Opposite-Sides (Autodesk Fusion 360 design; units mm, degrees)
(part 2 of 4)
sketch "Roller compensated wide travel cam" plane through (7, 0, 0) normal (1, 0, 0) x axis (0, 0, -1)
  line L1 (-46.7858, 45.5639) -> (-46.9806, 45.5802)
  line L2 (-46.6024, 45.5464) -> (-46.7858, 45.5639)
  line L3 (-46.4304, 45.5278) -> (-46.6024, 45.5464)
  line L4 (-46.2696, 45.5078) -> (-46.4304, 45.5278)
  line L5 (-46.1199, 45.4865) -> (-46.2696, 45.5078)
  line L6 (-45.9808, 45.464) -> (-46.1199, 45.4865)
  line L7 (-45.8519, 45.4403) -> (-45.9808, 45.464)
  line L8 (-45.7328, 45.4155) -> (-45.8519, 45.4403)
  line L9 (-45.6227, 45.3897) -> (-45.7328, 45.4155)
  line L10 (-45.5208, 45.363) -> (-45.6227, 45.3897)
  line L11 (-45.4263, 45.3354) -> (-45.5208, 45.363)
  line L12 (-45.3379, 45.3069) -> (-45.4263, 45.3354)
  line L13 (-45.2547, 45.2772) -> (-45.3379, 45.3069)
  line L14 (-45.1753, 45.2462) -> (-45.2547, 45.2772)
  line L15 (-45.0985, 45.2134) -> (-45.1753, 45.2462)
  line L16 (-45.023, 45.1784) -> (-45.0985, 45.2134)
  line L17 (-44.9476, 45.1406) -> (-45.023, 45.1784)
  line L18 (-44.8711, 45.0992) -> (-44.9476, 45.1406)
  line L19 (-44.7923, 45.0536) -> (-44.8711, 45.0992)
  line L20 (-44.7102, 45.0028) -> (-44.7923, 45.0536)
  line L21 (-44.6241, 44.9462) -> (-44.7102, 45.0028)
  line L22 (-44.5331, 44.8829) -> (-44.6241, 44.9462)
  line L23 (-44.4367, 44.8122) -> (-44.5331, 44.8829)
  line L24 (-44.3343, 44.7335) -> (-44.4367, 44.8122)
  line L25 (-44.2256, 44.6462) -> (-44.3343, 44.7335)
  line L26 (-44.1102, 44.5498) -> (-44.2256, 44.6462)
  line L27 (-43.988, 44.4442) -> (-44.1102, 44.5498)
  line L28 (-43.8587, 44.329) -> (-43.988, 44.4442)
  line L29 (-43.7222, 44.2043) -> (-43.8587, 44.329)
  line L30 (-43.5783, 44.0701) -> (-43.7222, 44.2043)
  line L31 (-43.4268, 43.9266) -> (-43.5783, 44.0701)
  line L32 (-43.2677, 43.7741) -> (-43.4268, 43.9266)
  line L33 (-43.1006, 43.6131) -> (-43.2677, 43.7741)
  line L34 (-42.9255, 43.4439) -> (-43.1006, 43.6131)
  line L35 (-42.742, 43.2673) -> (-42.9255, 43.4439)
  line L36 (-42.55, 43.084) -> (-42.742, 43.2673)
  line L37 (-42.3493, 42.8946) -> (-42.55, 43.084)
  line L38 (-42.1396, 42.7) -> (-42.3493, 42.8946)
  line L39 (-41.9208, 42.5013) -> (-42.1396, 42.7)
  line L40 (-41.6928, 42.2994) -> (-41.9208, 42.5013)
  line L41 (-41.4556, 42.0954) -> (-41.6928, 42.2994)
  line L42 (-41.2093, 41.8904) -> (-41.4556, 42.0954)
  line L43 (-40.9541, 41.6856) -> (-41.2093, 41.8904)
  line L44 (-40.6904, 41.4823) -> (-40.9541, 41.6856)
  line L45 (-40.4188, 41.2816) -> (-40.6904, 41.4823)
  line L46 (-40.1398, 41.0847) -> (-40.4188, 41.2816)
  line L47 (-39.8545, 40.8926) -> (-40.1398, 41.0847)
  line L48 (-39.5639, 40.7063) -> (-39.8545, 40.8926)
  line L49 (-39.2691, 40.5267) -> (-39.5639, 40.7063)
  line L50 (-38.9713, 40.3545) -> (-39.2691, 40.5267)
  line L51 (-38.6721, 40.1902) -> (-38.9713, 40.3545)
  line L52 (-38.3727, 40.034) -> (-38.6721, 40.1902)
  line L53 (-38.0744, 39.8861) -> (-38.3727, 40.034)
  line L54 (-37.7787, 39.7466) -> (-38.0744, 39.8861)
  line L55 (-37.4868, 39.6151) -> (-37.7787, 39.7466)
  line L56 (-37.1999, 39.4914) -> (-37.4868, 39.6151)
  line L57 (-36.9189, 39.3751) -> (-37.1999, 39.4914)
  line L58 (-36.645, 39.2655) -> (-36.9189, 39.3751)
  line L59 (-36.3788, 39.1623) -> (-36.645, 39.2655)
  line L60 (-36.1212, 39.0647) -> (-36.3788, 39.1623)
  line L61 (-35.8727, 38.9722) -> (-36.1212, 39.0647)
  line L62 (-35.6338, 38.8843) -> (-35.8727, 38.9722)
  line L63 (-35.4051, 38.8004) -> (-35.6338, 38.8843)
  line L64 (-35.1869, 38.7201) -> (-35.4051, 38.8004)
  line L65 (-34.9795, 38.6429) -> (-35.1869, 38.7201)
  line L66 (-34.7831, 38.5685) -> (-34.9795, 38.6429)
  line L67 (-34.5979, 38.4966) -> (-34.7831, 38.5685)
  line L68 (-34.4239, 38.427) -> (-34.5979, 38.4966)
  line L69 (-34.2612, 38.3594) -> (-34.4239, 38.427)
  line L70 (-34.1096, 38.2939) -> (-34.2612, 38.3594)
  line L71 (-33.969, 38.2303) -> (-34.1096, 38.2939)
  line L72 (-33.8391, 38.1685) -> (-33.969, 38.2303)
  line L73 (-33.7195, 38.1085) -> (-33.8391, 38.1685)
  line L74 (-33.6097, 38.0503) -> (-33.7195, 38.1085)
  line L75 (-33.5091, 37.9937) -> (-33.6097, 38.0503)
  line L76 (-33.4168, 37.9387) -> (-33.5091, 37.9937)
  line L77 (-33.3321, 37.885) -> (-33.4168, 37.9387)
  line L78 (-33.2539, 37.8322) -> (-33.3321, 37.885)
  line L79 (-33.1812, 37.78) -> (-33.2539, 37.8322)
  line L80 (-33.1129, 37.7277) -> (-33.1812, 37.78)
  line L81 (-33.0479, 37.6747) -> (-33.1129, 37.7277)
  line L82 (-32.9851, 37.6202) -> (-33.0479, 37.6747)
  line L83 (-32.9235, 37.5633) -> (-32.9851, 37.6202)
  line L84 (-32.862, 37.503) -> (-32.9235, 37.5633)
  line L85 (-32.7998, 37.4383) -> (-32.862, 37.503)
  line L86 (-32.7362, 37.368) -> (-32.7998, 37.4383)
  line L87 (-32.6705, 37.2912) -> (-32.7362, 37.368)
  line L88 (-32.6022, 37.2069) -> (-32.6705, 37.2912)
  line L89 (-32.5308, 37.1142) -> (-32.6022, 37.2069)
  line L90 (-32.4562, 37.0123) -> (-32.5308, 37.1142)
  line L91 (-32.3779, 36.9005) -> (-32.4562, 37.0123)
  line L92 (-32.2959, 36.7783) -> (-32.3779, 36.9005)
  line L93 (-32.21, 36.6453) -> (-32.2959, 36.7783)
  line L94 (-32.1201, 36.5013) -> (-32.21, 36.6453)
  line L95 (-32.0261, 36.346) -> (-32.1201, 36.5013)
  line L96 (-31.9277, 36.1795) -> (-32.0261, 36.346)
  line L97 (-31.8248, 36.002) -> (-31.9277, 36.1795)
  line L98 (-31.7171, 35.8135) -> (-31.8248, 36.002)
  line L99 (-31.6045, 35.6144) -> (-31.7171, 35.8135)
  line L100 (-31.4864, 35.4052) -> (-31.6045, 35.6144)
  line L101 (-31.3627, 35.1863) -> (-31.4864, 35.4052)
  line L102 (-31.2328, 34.9582) -> (-31.3627, 35.1863)
  line L103 (-31.0963, 34.7217) -> (-31.2328, 34.9582)
  line L104 (-30.9529, 34.4775) -> (-31.0963, 34.7217)
  line L105 (-30.8021, 34.2264) -> (-30.9529, 34.4775)
  line L106 (-30.6435, 33.9694) -> (-30.8021, 34.2264)
  line L107 (-30.4767, 33.7074) -> (-30.6435, 33.9694)
  line L108 (-30.3015, 33.4416) -> (-30.4767, 33.7074)
  line L109 (-30.1178, 33.1731) -> (-30.3015, 33.4416)
  line L110 (-29.9254, 32.9032) -> (-30.1178, 33.1731)
  line L111 (-29.7247, 32.6331) -> (-29.9254, 32.9032)
  line L112 (-29.5158, 32.3642) -> (-29.7247, 32.6331)
  line L113 (-29.2992, 32.0978) -> (-29.5158, 32.3642)
  line L114 (-29.0756, 31.8351) -> (-29.2992, 32.0978)
  line L115 (-28.8458, 31.5773) -> (-29.0756, 31.8351)
  line L116 (-28.6108, 31.3255) -> (-28.8458, 31.5773)
  line L117 (-28.3718, 31.0805) -> (-28.6108, 31.3255)
  line L118 (-28.13, 30.8431) -> (-28.3718, 31.0805)
  line L119 (-27.8865, 30.6139) -> (-28.13, 30.8431)
  line L120 (-27.6427, 30.3933) -> (-27.8865, 30.6139)
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extrude "Extrude1" new body sketch "Roller compensated wide travel cam" along normal blind 8 bodies "P08 Cam 8 gates - 116 degree span"
work_plane "WorkPlane2" AlongDistance 6.9 ExtraOffset 0
sketch "Cam screw clearance" plane through (6.9, 0, 0) normal (1, 0, 0) x axis (0, 0, -1)
  circle C1 centre (-39.5442, 25.4558) radius 1.7
extrude "Extrude2" cut sketch "Cam screw clearance" along normal blind 8.2
work_plane "WorkPlane3" AlongDistance 12 ExtraOffset 0
sketch "Cam head recess" plane through (12, 0, 0) normal (1, 0, 0) x axis (0, 0, -1)
  circle C1 centre (-39.5442, 25.4558) radius 3.1
extrude "Extrude3" cut sketch "Cam head recess" along normal blind 3.1
work_plane "WorkPlane4" AlongDistance 6.9 ExtraOffset 0
sketch "Cam screw clearance (1)" plane through (6.9, 0, 0) normal (1, 0, 0) x axis (0, 0, -1)
  circle C1 centre (-29, 0) radius 1.7
extrude "Extrude4" cut sketch "Cam screw clearance (1)" along normal blind 8.2
work_plane "WorkPlane5" AlongDistance 12 ExtraOffset 0
sketch "Cam head recess (1)" plane through (12, 0, 0) normal (1, 0, 0) x axis (0, 0, -1)
  circle C1 centre (-29, 0) radius 3.1
extrude "Extrude5" cut sketch "Cam head recess (1)" along normal blind 3.1
work_plane "WorkPlane6" AlongDistance 6.9 ExtraOffset 0
sketch "Cam screw clearance (2)" plane through (6.9, 0, 0) normal (1, 0, 0) x axis (0, 0, -1)
  circle C1 centre (-39.5442, -25.4558) radius 1.7
extrude "Extrude6" cut sketch "Cam screw clearance (2)" along normal blind 8.2
work_plane "WorkPlane7" AlongDistance 12 ExtraOffset 0
sketch "Cam head recess (2)" plane through (12, 0, 0) normal (1, 0, 0) x axis (0, 0, -1)
  circle C1 centre (-39.5442, -25.4558) radius 3.1
extrude "Extrude7" cut sketch "Cam head recess (2)" along normal blind 3.1
work_plane "WorkPlane1" AlongDistance 7 ExtraOffset 0
sketch "Roller compensated wide travel cam" plane through (7, 0, 0) normal (1, 0, 0) x axis (0, 0, -1)
  line L1 (-47.2232, 45.9898) -> (-47.3676, 46.0185)
  line L2 (-47.0847, 45.9596) -> (-47.2232, 45.9898)
  line L3 (-46.9517, 45.9277) -> (-47.0847, 45.9596)
  line L4 (-46.8237, 45.8942) -> (-46.9517, 45.9277)
  line L5 (-46.7004, 45.859) -> (-46.8237, 45.8942)
  line L6 (-46.5811, 45.822) -> (-46.7004, 45.859)
  line L7 (-46.4652, 45.7832) -> (-46.5811, 45.822)
  line L8 (-46.3522, 45.7423) -> (-46.4652, 45.7832)
  line L9 (-46.2414, 45.6993) -> (-46.3522, 45.7423)
  line L10 (-46.1322, 45.6539) -> (-46.2414, 45.6993)
  line L11 (-46.024, 45.6058) -> (-46.1322, 45.6539)
  line L12 (-45.916, 45.5547) -> (-46.024, 45.6058)
  line L13 (-45.8078, 45.5004) -> (-45.916, 45.5547)
  line L14 (-45.6986, 45.4424) -> (-45.8078, 45.5004)
  line L15 (-45.5881, 45.3805) -> (-45.6986, 45.4424)
  line L16 (-45.4756, 45.3143) -> (-45.5881, 45.3805)
  line L17 (-45.3607, 45.2433) -> (-45.4756, 45.3143)
  line L18 (-45.2431, 45.1673) -> (-45.3607, 45.2433)
  line L19 (-45.1224, 45.0861) -> (-45.2431, 45.1673)
  line L20 (-44.9982, 44.9992) -> (-45.1224, 45.0861)
  line L21 (-44.8704, 44.9065) -> (-44.9982, 44.9992)
  line L22 (-44.7386, 44.8078) -> (-44.8704, 44.9065)
  line L23 (-44.6027, 44.7029) -> (-44.7386, 44.8078)
  line L24 (-44.4626, 44.5919) -> (-44.6027, 44.7029)
  line L25 (-44.318, 44.4746) -> (-44.4626, 44.5919)
  line L26 (-44.1688, 44.3511) -> (-44.318, 44.4746)
  line L27 (-44.0149, 44.2214) -> (-44.1688, 44.3511)
  line L28 (-43.8562, 44.0858) -> (-44.0149, 44.2214)
  line L29 (-43.6926, 43.9444) -> (-43.8562, 44.0858)
  line L30 (-43.524, 43.7975) -> (-43.6926, 43.9444)
  line L31 (-43.3501, 43.6453) -> (-43.524, 43.7975)
  line L32 (-43.171, 43.4882) -> (-43.3501, 43.6453)
  line L33 (-42.9865, 43.3266) -> (-43.171, 43.4882)
  line L34 (-42.7965, 43.1608) -> (-42.9865, 43.3266)
  line L35 (-42.601, 42.9913) -> (-42.7965, 43.1608)
  line L36 (-42.3997, 42.8187) -> (-42.601, 42.9913)
  line L37 (-42.1927, 42.6433) -> (-42.3997, 42.8187)
  line L38 (-41.98, 42.4659) -> (-42.1927, 42.6433)
  line L39 (-41.7616, 42.2869) -> (-41.98, 42.4659)
  line L40 (-41.5374, 42.107) -> (-41.7616, 42.2869)
  line L41 (-41.3077, 41.9267) -> (-41.5374, 42.107)
  line L42 (-41.0725, 41.7467) -> (-41.3077, 41.9267)
  line L43 (-40.8321, 41.5676) -> (-41.0725, 41.7467)
  line L44 (-40.5867, 41.39) -> (-40.8321, 41.5676)
  line L45 (-40.3368, 41.2146) -> (-40.5867, 41.39)
  line L46 (-40.0826, 41.0418) -> (-40.3368, 41.2146)
  line L47 (-39.8248, 40.8722) -> (-40.0826, 41.0418)
  line L48 (-39.5639, 40.7063) -> (-39.8248, 40.8722)
  line L49 (-39.3004, 40.5445) -> (-39.5639, 40.7063)
  line L50 (-39.0349, 40.3871) -> (-39.3004, 40.5445)
  line L51 (-38.7682, 40.2345) -> (-39.0349, 40.3871)
  line L52 (-38.501, 40.0867) -> (-38.7682, 40.2345)
  line L53 (-38.2339, 39.9441) -> (-38.501, 40.0867)
  line L54 (-37.9676, 39.8065) -> (-38.2339, 39.9441)
  line L55 (-37.7028, 39.674) -> (-37.9676, 39.8065)
  line L56 (-37.4402, 39.5466) -> (-37.7028, 39.674)
  line L57 (-37.1804, 39.424) -> (-37.4402, 39.5466)
  line L58 (-36.9239, 39.3061) -> (-37.1804, 39.424)
  line L59 (-36.6714, 39.1927) -> (-36.9239, 39.3061)
  line L60 (-36.4233, 39.0834) -> (-36.6714, 39.1927)
  line L61 (-36.1801, 38.9781) -> (-36.4233, 39.0834)
  line L62 (-35.9423, 38.8763) -> (-36.1801, 38.9781)
  line L63 (-35.71, 38.7779) -> (-35.9423, 38.8763)
  line L64 (-35.4838, 38.6825) -> (-35.71, 38.7779)
  line L65 (-35.2639, 38.5899) -> (-35.4838, 38.6825)
  line L66 (-35.0505, 38.4997) -> (-35.2639, 38.5899)
  line L67 (-34.8439, 38.4117) -> (-35.0505, 38.4997)
  line L68 (-34.6443, 38.3257) -> (-34.8439, 38.4117)
  line L69 (-34.4517, 38.2414) -> (-34.6443, 38.3257)
  line L70 (-34.2663, 38.1586) -> (-34.4517, 38.2414)
  line L71 (-34.0882, 38.0773) -> (-34.2663, 38.1586)
  line L72 (-33.9174, 37.9972) -> (-34.0882, 38.0773)
  line L73 (-33.7538, 37.9181) -> (-33.9174, 37.9972)
  line L74 (-33.5975, 37.8401) -> (-33.7538, 37.9181)
  line L75 (-33.4483, 37.763) -> (-33.5975, 37.8401)
  line L76 (-33.3061, 37.6867) -> (-33.4483, 37.763)
  line L77 (-33.1706, 37.611) -> (-33.3061, 37.6867)
  line L78 (-33.0417, 37.536) -> (-33.1706, 37.611)
  line L79 (-32.919, 37.4615) -> (-33.0417, 37.536)
  line L80 (-32.8022, 37.3873) -> (-32.919, 37.4615)
  line L81 (-32.6908, 37.3133) -> (-32.8022, 37.3873)
  line L82 (-32.5845, 37.2393) -> (-32.6908, 37.3133)
  line L83 (-32.4827, 37.165) -> (-32.5845, 37.2393)
  line L84 (-32.385, 37.0903) -> (-32.4827, 37.165)
  line L85 (-32.2909, 37.0147) -> (-32.385, 37.0903)
  line L86 (-32.1997, 36.9379) -> (-32.2909, 37.0147)
  line L87 (-32.111, 36.8595) -> (-32.1997, 36.9379)
  line L88 (-32.0242, 36.7791) -> (-32.111, 36.8595)
  line L89 (-31.9389, 36.6961) -> (-32.0242, 36.7791)
  line L90 (-31.8545, 36.6101) -> (-31.9389, 36.6961)
  line L91 (-31.7707, 36.5206) -> (-31.8545, 36.6101)
  line L92 (-31.6869, 36.427) -> (-31.7707, 36.5206)
  line L93 (-31.6028, 36.3289) -> (-31.6869, 36.427)
  line L94 (-31.5182, 36.2257) -> (-31.6028, 36.3289)
  line L95 (-31.4327, 36.117) -> (-31.5182, 36.2257)
  line L96 (-31.3461, 36.0024) -> (-31.4327, 36.117)
  line L97 (-31.2582, 35.8815) -> (-31.3461, 36.0024)
  line L98 (-31.1688, 35.754) -> (-31.2582, 35.8815)
  line L99 (-31.0777, 35.6196) -> (-31.1688, 35.754)
  line L100 (-30.9848, 35.478) -> (-31.0777, 35.6196)
  line L101 (-30.89, 35.3293) -> (-30.9848, 35.478)
  line L102 (-30.7931, 35.1732) -> (-30.89, 35.3293)
  line L103 (-30.694, 35.0097) -> (-30.7931, 35.1732)
  line L104 (-30.5926, 34.8389) -> (-30.694, 35.0097)
  line L105 (-30.4886, 34.6608) -> (-30.5926, 34.8389)
  line L106 (-30.382, 34.4756) -> (-30.4886, 34.6608)
  line L107 (-30.2724, 34.2834) -> (-30.382, 34.4756)
  line L108 (-30.1599, 34.0844) -> (-30.2724, 34.2834)
  line L109 (-30.044, 33.879) -> (-30.1599, 34.0844)
  line L110 (-29.9247, 33.6673) -> (-30.044, 33.879)
  line L111 (-29.8016, 33.4498) -> (-29.9247, 33.6673)
  line L112 (-29.6745, 33.2269) -> (-29.8016, 33.4498)
  line L113 (-29.5432, 32.999) -> (-29.6745, 33.2269)
  line L114 (-29.4075, 32.7664) -> (-29.5432, 32.999)
  line L115 (-29.2671, 32.5298) -> (-29.4075, 32.7664)
  line L116 (-29.1219, 32.2896) -> (-29.2671, 32.5298)
  line L117 (-28.9716, 32.0465) -> (-29.1219, 32.2896)
  line L118 (-28.8163, 31.801) -> (-28.9716, 32.0465)
  line L119 (-28.6557, 31.5537) -> (-28.8163, 31.801)
  line L120 (-28.4898, 31.3054) -> (-28.6557, 31.5537)
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extrude "Extrude1" new body sketch "Roller compensated wide travel cam" along normal blind 8 bodies "P08 Cam 7 gates - 116 degree span"
work_plane "WorkPlane2" AlongDistance 6.9 ExtraOffset 0
sketch "Cam screw clearance" plane through (6.9, 0, 0) normal (1, 0, 0) x axis (0, 0, -1)
  circle C1 centre (-39.5442, 25.4558) radius 1.7
extrude "Extrude2" cut sketch "Cam screw clearance" along normal blind 8.2
work_plane "WorkPlane3" AlongDistance 12 ExtraOffset 0
sketch "Cam head recess" plane through (12, 0, 0) normal (1, 0, 0) x axis (0, 0, -1)
  circle C1 centre (-39.5442, 25.4558) radius 3.1
extrude "Extrude3" cut sketch "Cam head recess" along normal blind 3.1
work_plane "WorkPlane4" AlongDistance 6.9 ExtraOffset 0
sketch "Cam screw clearance (1)" plane through (6.9, 0, 0) normal (1, 0, 0) x axis (0, 0, -1)
  circle C1 centre (-29, 0) radius 1.7
extrude "Extrude4" cut sketch "Cam screw clearance (1)" along normal blind 8.2
work_plane "WorkPlane5" AlongDistance 12 ExtraOffset 0
sketch "Cam head recess (1)" plane through (12, 0, 0) normal (1, 0, 0) x axis (0, 0, -1)
  circle C1 centre (-29, 0) radius 3.1
extrude "Extrude5" cut sketch "Cam head recess (1)" along normal blind 3.1
work_plane "WorkPlane6" AlongDistance 6.9 ExtraOffset 0
sketch "Cam screw clearance (2)" plane through (6.9, 0, 0) normal (1, 0, 0) x axis (0, 0, -1)
  circle C1 centre (-39.5442, -25.4558) radius 1.7
extrude "Extrude6" cut sketch "Cam screw clearance (2)" along normal blind 8.2
work_plane "WorkPlane7" AlongDistance 12 ExtraOffset 0
sketch "Cam head recess (2)" plane through (12, 0, 0) normal (1, 0, 0) x axis (0, 0, -1)
  circle C1 centre (-39.5442, -25.4558) radius 3.1
extrude "Extrude7" cut sketch "Cam head recess (2)" along normal blind 3.1
work_plane "WorkPlane1" AlongDistance 7 ExtraOffset 0
sketch "Roller compensated wide travel cam" plane through (7, 0, 0) normal (1, 0, 0) x axis (0, 0, -1)
  line L1 (-48.3375, 46.4002) -> (-48.4993, 46.476)
  line L2 (-48.1754, 46.322) -> (-48.3375, 46.4002)
  line L3 (-48.0129, 46.2414) -> (-48.1754, 46.322)
  line L4 (-47.8499, 46.1582) -> (-48.0129, 46.2414)
  line L5 (-47.6864, 46.0726) -> (-47.8499, 46.1582)
  line L6 (-47.5223, 45.9845) -> (-47.6864, 46.0726)
  line L7 (-47.3575, 45.8939) -> (-47.5223, 45.9845)
  line L8 (-47.1919, 45.8008) -> (-47.3575, 45.8939)
  line L9 (-47.0255, 45.7052) -> (-47.1919, 45.8008)
  line L10 (-46.8583, 45.6071) -> (-47.0255, 45.7052)
  line L11 (-46.6901, 45.5066) -> (-46.8583, 45.6071)
  line L12 (-46.5209, 45.4036) -> (-46.6901, 45.5066)
  line L13 (-46.3508, 45.2982) -> (-46.5209, 45.4036)
  line L14 (-46.1795, 45.1905) -> (-46.3508, 45.2982)
  line L15 (-46.0072, 45.0804) -> (-46.1795, 45.1905)
  line L16 (-45.8337, 44.9681) -> (-46.0072, 45.0804)
  line L17 (-45.659, 44.8535) -> (-45.8337, 44.9681)
  line L18 (-45.4831, 44.7368) -> (-45.659, 44.8535)
  line L19 (-45.3059, 44.618) -> (-45.4831, 44.7368)
  line L20 (-45.1274, 44.4972) -> (-45.3059, 44.618)
  line L21 (-44.9476, 44.3744) -> (-45.1274, 44.4972)
  line L22 (-44.7665, 44.2498) -> (-44.9476, 44.3744)
  line L23 (-44.584, 44.1234) -> (-44.7665, 44.2498)
  line L24 (-44.4001, 43.9953) -> (-44.584, 44.1234)
  line L25 (-44.2147, 43.8656) -> (-44.4001, 43.9953)
  line L26 (-44.0279, 43.7345) -> (-44.2147, 43.8656)
  line L27 (-43.8397, 43.602) -> (-44.0279, 43.7345)
  line L28 (-43.6499, 43.4683) -> (-43.8397, 43.602)
  line L29 (-43.4587, 43.3333) -> (-43.6499, 43.4683)
  line L30 (-43.266, 43.1974) -> (-43.4587, 43.3333)
  line L31 (-43.0719, 43.0605) -> (-43.266, 43.1974)
  line L32 (-42.8762, 42.9229) -> (-43.0719, 43.0605)
  line L33 (-42.679, 42.7845) -> (-42.8762, 42.9229)
  line L34 (-42.4804, 42.6456) -> (-42.679, 42.7845)
  line L35 (-42.2803, 42.5062) -> (-42.4804, 42.6456)
  line L36 (-42.0787, 42.3665) -> (-42.2803, 42.5062)
  line L37 (-41.8758, 42.2266) -> (-42.0787, 42.3665)
  line L38 (-41.6714, 42.0867) -> (-41.8758, 42.2266)
  line L39 (-41.4658, 41.9467) -> (-41.6714, 42.0867)
  line L40 (-41.2588, 41.8069) -> (-41.4658, 41.9467)
  line L41 (-41.0506, 41.6674) -> (-41.2588, 41.8069)
  line L42 (-40.8412, 41.5282) -> (-41.0506, 41.6674)
  line L43 (-40.6306, 41.3895) -> (-40.8412, 41.5282)
  line L44 (-40.4191, 41.2514) -> (-40.6306, 41.3895)
  line L45 (-40.2065, 41.1139) -> (-40.4191, 41.2514)
  line L46 (-39.9931, 40.9772) -> (-40.2065, 41.1139)
  line L47 (-39.7788, 40.8413) -> (-39.9931, 40.9772)
  line L48 (-39.5639, 40.7063) -> (-39.7788, 40.8413)
  line L49 (-39.3483, 40.5723) -> (-39.5639, 40.7063)
  line L50 (-39.1323, 40.4393) -> (-39.3483, 40.5723)
  line L51 (-38.9158, 40.3074) -> (-39.1323, 40.4393)
  line L52 (-38.6991, 40.1766) -> (-38.9158, 40.3074)
  line L53 (-38.4822, 40.047) -> (-38.6991, 40.1766)
  line L54 (-38.2652, 39.9186) -> (-38.4822, 40.047)
  line L55 (-38.0483, 39.7914) -> (-38.2652, 39.9186)
  line L56 (-37.8316, 39.6654) -> (-38.0483, 39.7914)
  line L57 (-37.6152, 39.5406) -> (-37.8316, 39.6654)
  line L58 (-37.3993, 39.4171) -> (-37.6152, 39.5406)
  line L59 (-37.1839, 39.2948) -> (-37.3993, 39.4171)
  line L60 (-36.9692, 39.1737) -> (-37.1839, 39.2948)
  line L61 (-36.7552, 39.0537) -> (-36.9692, 39.1737)
  line L62 (-36.5422, 38.9349) -> (-36.7552, 39.0537)
  line L63 (-36.3302, 38.8171) -> (-36.5422, 38.9349)
  line L64 (-36.1193, 38.7005) -> (-36.3302, 38.8171)
  line L65 (-35.9097, 38.5848) -> (-36.1193, 38.7005)
  line L66 (-35.7014, 38.4701) -> (-35.9097, 38.5848)
  line L67 (-35.4946, 38.3563) -> (-35.7014, 38.4701)
  line L68 (-35.2893, 38.2434) -> (-35.4946, 38.3563)
  line L69 (-35.0856, 38.1312) -> (-35.2893, 38.2434)
  line L70 (-34.8837, 38.0198) -> (-35.0856, 38.1312)
  line L71 (-34.6836, 37.909) -> (-34.8837, 38.0198)
  line L72 (-34.4855, 37.7988) -> (-34.6836, 37.909)
  line L73 (-34.2892, 37.6891) -> (-34.4855, 37.7988)
  line L74 (-34.0951, 37.5799) -> (-34.2892, 37.6891)
  line L75 (-33.9031, 37.4711) -> (-34.0951, 37.5799)
  line L76 (-33.7132, 37.3627) -> (-33.9031, 37.4711)
  line L77 (-33.5256, 37.2545) -> (-33.7132, 37.3627)
  line L78 (-33.3403, 37.1465) -> (-33.5256, 37.2545)
  line L79 (-33.1574, 37.0387) -> (-33.3403, 37.1465)
  line L80 (-32.9768, 36.931) -> (-33.1574, 37.0387)
  line L81 (-32.7987, 36.8233) -> (-32.9768, 36.931)
  line L82 (-32.6231, 36.7155) -> (-32.7987, 36.8233)
  line L83 (-32.45, 36.6077) -> (-32.6231, 36.7155)
  line L84 (-32.2794, 36.4998) -> (-32.45, 36.6077)
  line L85 (-32.1114, 36.3916) -> (-32.2794, 36.4998)
  line L86 (-31.9459, 36.2832) -> (-32.1114, 36.3916)
  line L87 (-31.7831, 36.1746) -> (-31.9459, 36.2832)
  line L88 (-31.6228, 36.0656) -> (-31.7831, 36.1746)
  line L89 (-31.465, 35.9562) -> (-31.6228, 36.0656)
  line L90 (-31.3099, 35.8463) -> (-31.465, 35.9562)
  line L91 (-31.1573, 35.736) -> (-31.3099, 35.8463)
  line L92 (-31.0072, 35.6251) -> (-31.1573, 35.736)
  line L93 (-30.8597, 35.5137) -> (-31.0072, 35.6251)
  line L94 (-30.7146, 35.4016) -> (-30.8597, 35.5137)
  line L95 (-30.5719, 35.2888) -> (-30.7146, 35.4016)
  line L96 (-30.4317, 35.1753) -> (-30.5719, 35.2888)
  line L97 (-30.2938, 35.061) -> (-30.4317, 35.1753)
  line L98 (-30.1583, 34.9458) -> (-30.2938, 35.061)
  line L99 (-30.0249, 34.8297) -> (-30.1583, 34.9458)
  line L100 (-29.8938, 34.7126) -> (-30.0249, 34.8297)
  line L101 (-29.7648, 34.5945) -> (-29.8938, 34.7126)
  line L102 (-29.6379, 34.4753) -> (-29.7648, 34.5945)
  line L103 (-29.5129, 34.3549) -> (-29.6379, 34.4753)
  line L104 (-29.3899, 34.2333) -> (-29.5129, 34.3549)
  line L105 (-29.2687, 34.1104) -> (-29.3899, 34.2333)
  line L106 (-29.1493, 33.986) -> (-29.2687, 34.1104)
  line L107 (-29.0316, 33.8602) -> (-29.1493, 33.986)
  line L108 (-28.9155, 33.7329) -> (-29.0316, 33.8602)
  line L109 (-28.8009, 33.6039) -> (-28.9155, 33.7329)
  line L110 (-28.6878, 33.4732) -> (-28.8009, 33.6039)
  line L111 (-28.5762, 33.3408) -> (-28.6878, 33.4732)
  line L112 (-28.4658, 33.2065) -> (-28.5762, 33.3408)
  line L113 (-28.3567, 33.0702) -> (-28.4658, 33.2065)
  line L114 (-28.2488, 32.932) -> (-28.3567, 33.0702)
  line L115 (-28.142, 32.7916) -> (-28.2488, 32.932)
  line L116 (-28.0362, 32.6491) -> (-28.142, 32.7916)
  line L117 (-27.9314, 32.5044) -> (-28.0362, 32.6491)
  line L118 (-27.8275, 32.3574) -> (-27.9314, 32.5044)
  line L119 (-27.7245, 32.2081) -> (-27.8275, 32.3574)
  line L120 (-27.6223, 32.0564) -> (-27.7245, 32.2081)
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extrude "Extrude1" new body sketch "Roller compensated wide travel cam" along normal blind 8 bodies "P08 Cam 5 gates - 116 degree span"
work_plane "WorkPlane2" AlongDistance 6.9 ExtraOffset 0
sketch "Cam screw clearance" plane through (6.9, 0, 0) normal (1, 0, 0) x axis (0, 0, -1)
  circle C1 centre (-39.5442, 25.4558) radius 1.7
extrude "Extrude2" cut sketch "Cam screw clearance" along normal blind 8.2
work_plane "WorkPlane3" AlongDistance 12 ExtraOffset 0
sketch "Cam head recess" plane through (12, 0, 0) normal (1, 0, 0) x axis (0, 0, -1)
  circle C1 centre (-39.5442, 25.4558) radius 3.1
extrude "Extrude3" cut sketch "Cam head recess" along normal blind 3.1
work_plane "WorkPlane4" AlongDistance 6.9 ExtraOffset 0
sketch "Cam screw clearance (1)" plane through (6.9, 0, 0) normal (1, 0, 0) x axis (0, 0, -1)
  circle C1 centre (-29, 0) radius 1.7
extrude "Extrude4" cut sketch "Cam screw clearance (1)" along normal blind 8.2
work_plane "WorkPlane5" AlongDistance 12 ExtraOffset 0
sketch "Cam head recess (1)" plane through (12, 0, 0) normal (1, 0, 0) x axis (0, 0, -1)
  circle C1 centre (-29, 0) radius 3.1
extrude "Extrude5" cut sketch "Cam head recess (1)" along normal blind 3.1
work_plane "WorkPlane6" AlongDistance 6.9 ExtraOffset 0
sketch "Cam screw clearance (2)" plane through (6.9, 0, 0) normal (1, 0, 0) x axis (0, 0, -1)
  circle C1 centre (-39.5442, -25.4558) radius 1.7
extrude "Extrude6" cut sketch "Cam screw clearance (2)" along normal blind 8.2
work_plane "WorkPlane7" AlongDistance 12 ExtraOffset 0
sketch "Cam head recess (2)" plane through (12, 0, 0) normal (1, 0, 0) x axis (0, 0, -1)
  circle C1 centre (-39.5442, -25.4558) radius 3.1
extrude "Extrude7" cut sketch "Cam head recess (2)" along normal blind 3.1
work_plane "WorkPlane1" AlongDistance 7 ExtraOffset 0
sketch "Roller compensated wide travel cam" plane through (7, 0, 0) normal (1, 0, 0) x axis (0, 0, -1)
  line L1 (-48.5705, 45.6443) -> (-48.7661, 45.7338)
  line L2 (-48.3751, 45.554) -> (-48.5705, 45.6443)
  line L3 (-48.1798, 45.4628) -> (-48.3751, 45.554)
  line L4 (-47.9847, 45.3709) -> (-48.1798, 45.4628)
  line L5 (-47.7898, 45.2782) -> (-47.9847, 45.3709)
  line L6 (-47.595, 45.1848) -> (-47.7898, 45.2782)
  line L7 (-47.4003, 45.0906) -> (-47.595, 45.1848)
  line L8 (-47.2058, 44.9956) -> (-47.4003, 45.0906)
  line L9 (-47.0114, 44.8999) -> (-47.2058, 44.9956)
  line L10 (-46.8172, 44.8035) -> (-47.0114, 44.8999)
  line L11 (-46.6232, 44.7064) -> (-46.8172, 44.8035)
  line L12 (-46.4293, 44.6085) -> (-46.6232, 44.7064)
  line L13 (-46.2355, 44.51) -> (-46.4293, 44.6085)
  line L14 (-46.0419, 44.4108) -> (-46.2355, 44.51)
  line L15 (-45.8485, 44.311) -> (-46.0419, 44.4108)
  line L16 (-45.6552, 44.2105) -> (-45.8485, 44.311)
  line L17 (-45.4621, 44.1093) -> (-45.6552, 44.2105)
  line L18 (-45.2692, 44.0075) -> (-45.4621, 44.1093)
  line L19 (-45.0764, 43.9051) -> (-45.2692, 44.0075)
  line L20 (-44.8837, 43.8021) -> (-45.0764, 43.9051)
  line L21 (-44.6913, 43.6985) -> (-44.8837, 43.8021)
  line L22 (-44.4989, 43.5943) -> (-44.6913, 43.6985)
  line L23 (-44.3068, 43.4895) -> (-44.4989, 43.5943)
  line L24 (-44.1148, 43.3841) -> (-44.3068, 43.4895)
  line L25 (-43.923, 43.2782) -> (-44.1148, 43.3841)
  line L26 (-43.7314, 43.1717) -> (-43.923, 43.2782)
  line L27 (-43.5399, 43.0647) -> (-43.7314, 43.1717)
  line L28 (-43.3486, 42.9572) -> (-43.5399, 43.0647)
  line L29 (-43.1575, 42.8491) -> (-43.3486, 42.9572)
  line L30 (-42.9666, 42.7405) -> (-43.1575, 42.8491)
  line L31 (-42.7758, 42.6314) -> (-42.9666, 42.7405)
  line L32 (-42.5853, 42.5218) -> (-42.7758, 42.6314)
  line L33 (-42.3949, 42.4118) -> (-42.5853, 42.5218)
  line L34 (-42.2047, 42.3012) -> (-42.3949, 42.4118)
  line L35 (-42.0147, 42.1902) -> (-42.2047, 42.3012)
  line L36 (-41.8249, 42.0787) -> (-42.0147, 42.1902)
  line L37 (-41.6353, 41.9667) -> (-41.8249, 42.0787)
  line L38 (-41.4459, 41.8543) -> (-41.6353, 41.9667)
  line L39 (-41.2567, 41.7414) -> (-41.4459, 41.8543)
  line L40 (-41.0677, 41.6281) -> (-41.2567, 41.7414)
  line L41 (-40.8789, 41.5144) -> (-41.0677, 41.6281)
  line L42 (-40.6904, 41.4002) -> (-40.8789, 41.5144)
  line L43 (-40.502, 41.2856) -> (-40.6904, 41.4002)
  line L44 (-40.3139, 41.1705) -> (-40.502, 41.2856)
  line L45 (-40.1261, 41.0551) -> (-40.3139, 41.1705)
  line L46 (-39.9384, 40.9392) -> (-40.1261, 41.0551)
  line L47 (-39.751, 40.823) -> (-39.9384, 40.9392)
  line L48 (-39.5639, 40.7063) -> (-39.751, 40.823)
  line L49 (-39.377, 40.5892) -> (-39.5639, 40.7063)
  line L50 (-39.1903, 40.4718) -> (-39.377, 40.5892)
  line L51 (-39.0039, 40.3539) -> (-39.1903, 40.4718)
  line L52 (-38.8178, 40.2357) -> (-39.0039, 40.3539)
  line L53 (-38.632, 40.117) -> (-38.8178, 40.2357)
  line L54 (-38.4464, 39.998) -> (-38.632, 40.117)
  line L55 (-38.2611, 39.8786) -> (-38.4464, 39.998)
  line L56 (-38.0761, 39.7588) -> (-38.2611, 39.8786)
  line L57 (-37.8914, 39.6386) -> (-38.0761, 39.7588)
  line L58 (-37.7071, 39.518) -> (-37.8914, 39.6386)
  line L59 (-37.523, 39.3971) -> (-37.7071, 39.518)
  line L60 (-37.3392, 39.2757) -> (-37.523, 39.3971)
  line L61 (-37.1558, 39.154) -> (-37.3392, 39.2757)
  line L62 (-36.9727, 39.0319) -> (-37.1558, 39.154)
  line L63 (-36.7899, 38.9094) -> (-36.9727, 39.0319)
  line L64 (-36.6075, 38.7865) -> (-36.7899, 38.9094)
  line L65 (-36.4255, 38.6633) -> (-36.6075, 38.7865)
  line L66 (-36.2438, 38.5396) -> (-36.4255, 38.6633)
  line L67 (-36.0625, 38.4156) -> (-36.2438, 38.5396)
  line L68 (-35.8815, 38.2912) -> (-36.0625, 38.4156)
  line L69 (-35.701, 38.1664) -> (-35.8815, 38.2912)
  line L70 (-35.5208, 38.0412) -> (-35.701, 38.1664)
  line L71 (-35.3411, 37.9156) -> (-35.5208, 38.0412)
  line L72 (-35.1617, 37.7896) -> (-35.3411, 37.9156)
  line L73 (-34.9828, 37.6631) -> (-35.1617, 37.7896)
  line L74 (-34.8044, 37.5363) -> (-34.9828, 37.6631)
  line L75 (-34.6263, 37.4091) -> (-34.8044, 37.5363)
  line L76 (-34.4487, 37.2815) -> (-34.6263, 37.4091)
  line L77 (-34.2716, 37.1534) -> (-34.4487, 37.2815)
  line L78 (-34.095, 37.0249) -> (-34.2716, 37.1534)
  line L79 (-33.9188, 36.896) -> (-34.095, 37.0249)
  line L80 (-33.7431, 36.7667) -> (-33.9188, 36.896)
  line L81 (-33.5679, 36.6369) -> (-33.7431, 36.7667)
  line L82 (-33.3933, 36.5067) -> (-33.5679, 36.6369)
  line L83 (-33.2191, 36.3761) -> (-33.3933, 36.5067)
  line L84 (-33.0455, 36.245) -> (-33.2191, 36.3761)
  line L85 (-32.8724, 36.1134) -> (-33.0455, 36.245)
  line L86 (-32.6998, 35.9814) -> (-32.8724, 36.1134)
  line L87 (-32.5279, 35.8489) -> (-32.6998, 35.9814)
  line L88 (-32.3565, 35.716) -> (-32.5279, 35.8489)
  line L89 (-32.1856, 35.5826) -> (-32.3565, 35.716)
  line L90 (-32.0154, 35.4487) -> (-32.1856, 35.5826)
  line L91 (-31.8458, 35.3144) -> (-32.0154, 35.4487)
  line L92 (-31.6768, 35.1795) -> (-31.8458, 35.3144)
  line L93 (-31.5084, 35.0442) -> (-31.6768, 35.1795)
  line L94 (-31.3406, 34.9083) -> (-31.5084, 35.0442)
  line L95 (-31.1735, 34.772) -> (-31.3406, 34.9083)
  line L96 (-31.0071, 34.6351) -> (-31.1735, 34.772)
  line L97 (-30.8413, 34.4977) -> (-31.0071, 34.6351)
  line L98 (-30.6762, 34.3598) -> (-30.8413, 34.4977)
  line L99 (-30.5118, 34.2214) -> (-30.6762, 34.3598)
  line L100 (-30.3481, 34.0825) -> (-30.5118, 34.2214)
  line L101 (-30.1851, 33.943) -> (-30.3481, 34.0825)
  line L102 (-30.0228, 33.803) -> (-30.1851, 33.943)
  line L103 (-29.8612, 33.6624) -> (-30.0228, 33.803)
  line L104 (-29.7004, 33.5213) -> (-29.8612, 33.6624)
  line L105 (-29.5404, 33.3796) -> (-29.7004, 33.5213)
  line L106 (-29.3811, 33.2374) -> (-29.5404, 33.3796)
  line L107 (-29.2226, 33.0946) -> (-29.3811, 33.2374)
  line L108 (-29.0649, 32.9512) -> (-29.2226, 33.0946)
  line L109 (-28.908, 32.8073) -> (-29.0649, 32.9512)
  line L110 (-28.7519, 32.6628) -> (-28.908, 32.8073)
  line L111 (-28.5966, 32.5177) -> (-28.7519, 32.6628)
  line L112 (-28.4422, 32.372) -> (-28.5966, 32.5177)
  line L113 (-28.2886, 32.2257) -> (-28.4422, 32.372)
  line L114 (-28.1358, 32.0788) -> (-28.2886, 32.2257)
  line L115 (-27.984, 31.9314) -> (-28.1358, 32.0788)
  line L116 (-27.833, 31.7833) -> (-27.984, 31.9314)
  line L117 (-27.6828, 31.6346) -> (-27.833, 31.7833)
  line L118 (-27.5336, 31.4853) -> (-27.6828, 31.6346)
  line L119 (-27.3853, 31.3354) -> (-27.5336, 31.4853)
  line L120 (-27.2379, 31.1849) -> (-27.3853, 31.3354)
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extrude "Extrude1" new body sketch "Roller compensated wide travel cam" along normal blind 8 bodies "P08 Cam 3 gates - 116 degree span"
work_plane "WorkPlane2" AlongDistance 6.9 ExtraOffset 0
sketch "Cam screw clearance" plane through (6.9, 0, 0) normal (1, 0, 0) x axis (0, 0, -1)
  circle C1 centre (-39.5442, 25.4558) radius 1.7
extrude "Extrude2" cut sketch "Cam screw clearance" along normal blind 8.2
work_plane "WorkPlane3" AlongDistance 12 ExtraOffset 0
sketch "Cam head recess" plane through (12, 0, 0) normal (1, 0, 0) x axis (0, 0, -1)
  circle C1 centre (-39.5442, 25.4558) radius 3.1
extrude "Extrude3" cut sketch "Cam head recess" along normal blind 3.1
work_plane "WorkPlane4" AlongDistance 6.9 ExtraOffset 0
sketch "Cam screw clearance (1)" plane through (6.9, 0, 0) normal (1, 0, 0) x axis (0, 0, -1)
  circle C1 centre (-29, 0) radius 1.7
extrude "Extrude4" cut sketch "Cam screw clearance (1)" along normal blind 8.2
work_plane "WorkPlane5" AlongDistance 12 ExtraOffset 0
sketch "Cam head recess (1)" plane through (12, 0, 0) normal (1, 0, 0) x axis (0, 0, -1)
  circle C1 centre (-29, 0) radius 3.1
extrude "Extrude5" cut sketch "Cam head recess (1)" along normal blind 3.1
work_plane "WorkPlane6" AlongDistance 6.9 ExtraOffset 0
sketch "Cam screw clearance (2)" plane through (6.9, 0, 0) normal (1, 0, 0) x axis (0, 0, -1)
  circle C1 centre (-39.5442, -25.4558) radius 1.7
extrude "Extrude6" cut sketch "Cam screw clearance (2)" along normal blind 8.2
work_plane "WorkPlane7" AlongDistance 12 ExtraOffset 0
sketch "Cam head recess (2)" plane through (12, 0, 0) normal (1, 0, 0) x axis (0, 0, -1)
  circle C1 centre (-39.5442, -25.4558) radius 3.1
extrude "Extrude7" cut sketch "Cam head recess (2)" along normal blind 3.1
work_plane "WorkPlane1" AlongDistance 27.4 ExtraOffset 0
sketch "Measured body 11.2 x 9.5 x 6.6 excluding terminals" plane through (27.4, 0, 0) normal (1, 0, 0) x axis (0, 0, -1)
  line L1 (-105.4, 5.6) -> (-105.4, -5.6)
  line L2 (-114.9, 5.6) -> (-105.4, 5.6)
  line L3 (-114.9, -5.6) -> (-114.9, 5.6)
  line L4 (-105.4, -5.6) -> (-114.9, -5.6)
extrude "Extrude1" new body sketch "Measured body 11.2 x 9.5 x 6.6 excluding terminals" along normal blind 6.6 bodies "REFERENCE Geared pot user measured 2026-10-25"
work_plane "WorkPlane2" AlongDistance 34 ExtraOffset 0
sketch "M7 bushing length inferred 15 minus 8" plane through (34, 0, 0) normal (1, 0, 0) x axis (0, 0, -1)
  circle C1 centre (-110.15, 0) radius 3.5
extrude "Extrude2" add sketch "M7 bushing length inferred 15 minus 8" along normal blind 7
work_plane "WorkPlane3" AlongDistance 41 ExtraOffset 0
sketch "Measured rotating shaft diameter6 length8" plane through (41, 0, 0) normal (1, 0, 0) x axis (0, 0, -1)
  circle C1 centre (-110.15, 0) radius 3
extrude "Extrude3" add sketch "Measured rotating shaft diameter6 length8" along normal blind 8
position "Position5"
position "Position6"
work_plane "WorkPlane1" AlongDistance -24 ExtraOffset 0
sketch "Continuous load-bearing web" plane through (-24, 0, 0) normal (1, 0, 0) x axis (0, 0, -1)
  line L1 (-51.6257, 74.4508) -> (-51, 74.5)
  line L2 (-52.2361, 74.3042) -> (-51.6257, 74.4508)
  line L3 (-52.816, 74.064) -> (-52.2361, 74.3042)
  line L4 (-53.3511, 73.7361) -> (-52.816, 74.064)
  line L5 (-53.8284, 73.3284) -> (-53.3511, 73.7361)
  line L6 (-54.2361, 72.8511) -> (-53.8284, 73.3284)
  line L7 (-54.564, 72.316) -> (-54.2361, 72.8511)
  line L8 (-54.8042, 71.7361) -> (-54.564, 72.316)
  line L9 (-54.9508, 71.1257) -> (-54.8042, 71.7361)
  line L10 (-55, 70.5) -> (-54.9508, 71.1257)
  line L11 (-55, -70.5) -> (-55, 70.5)
  line L12 (-54.9508, -71.1257) -> (-55, -70.5)
  line L13 (-54.8042, -71.7361) -> (-54.9508, -71.1257)
  line L14 (-54.564, -72.316) -> (-54.8042, -71.7361)
  line L15 (-54.2361, -72.8511) -> (-54.564, -72.316)
  line L16 (-53.8284, -73.3284) -> (-54.2361, -72.8511)
  line L17 (-53.3511, -73.7361) -> (-53.8284, -73.3284)
  line L18 (-52.816, -74.064) -> (-53.3511, -73.7361)
  line L19 (-52.2361, -74.3042) -> (-52.816, -74.064)
  line L20 (-51.6257, -74.4508) -> (-52.2361, -74.3042)
  line L21 (-51, -74.5) -> (-51.6257, -74.4508)
  line L22 (33, -74.5) -> (-51, -74.5)
  line L23 (33.6257, -74.4508) -> (33, -74.5)
  line L24 (34.2361, -74.3042) -> (33.6257, -74.4508)
  line L25 (34.816, -74.064) -> (34.2361, -74.3042)
  line L26 (35.3511, -73.7361) -> (34.816, -74.064)
  line L27 (35.8284, -73.3284) -> (35.3511, -73.7361)
  line L28 (36.2361, -72.8511) -> (35.8284, -73.3284)
  line L29 (36.564, -72.316) -> (36.2361, -72.8511)
  line L30 (36.8042, -71.7361) -> (36.564, -72.316)
  line L31 (36.9508, -71.1257) -> (36.8042, -71.7361)
  line L32 (37, -70.5) -> (36.9508, -71.1257)
  line L33 (37, 70.5) -> (37, -70.5)
  line L34 (36.9508, 71.1257) -> (37, 70.5)
  line L35 (36.8042, 71.7361) -> (36.9508, 71.1257)
  line L36 (36.564, 72.316) -> (36.8042, 71.7361)
  line L37 (36.2361, 72.8511) -> (36.564, 72.316)
  line L38 (35.8284, 73.3284) -> (36.2361, 72.8511)
  line L39 (35.3511, 73.7361) -> (35.8284, 73.3284)
  line L40 (34.816, 74.064) -> (35.3511, 73.7361)
  line L41 (34.2361, 74.3042) -> (34.816, 74.064)
  line L42 (33.6257, 74.4508) -> (34.2361, 74.3042)
  line L43 (33, 74.5) -> (33.6257, 74.4508)
  line L44 (-51, 74.5) -> (33, 74.5)
extrude "Extrude1" new body sketch "Continuous load-bearing web" along normal blind 12 bodies "P01S Continuous left structural plate"
work_plane "WorkPlane2" AlongDistance -24 ExtraOffset 0
sketch "Broad rail tab root" plane through (-24, 0, 0) normal (1, 0, 0) x axis (0, 0, -1)
  line L1 (-51, -60) -> (-51, -95)
  line L2 (-64, -60) -> (-51, -60)
  line L3 (-64, -95) -> (-64, -60)
  line L4 (-51, -95) -> (-64, -95)
extrude "Extrude2" add sketch "Broad rail tab root" along normal blind 12
work_plane "WorkPlane3" AlongDistance -24.1 ExtraOffset 0
sketch "Rail seat underside" plane through (-24.1, 0, 0) normal (1, 0, 0) x axis (0, 0, -1)
  line L1 (-50.9, -75) -> (-50.9, -96)
  line L2 (-55, -75) -> (-50.9, -75)
  line L3 (-55, -96) -> (-55, -75)
  line L4 (-50.9, -96) -> (-55, -96)
extrude "Extrude3" cut sketch "Rail seat underside" along normal blind 12.2
work_plane "WorkPlane4" AlongDistance 54.9 ExtraOffset 0
sketch "M5 rail bore" plane through (0, 0, 54.9) normal (0, 0, 1) x axis (1, 0, 0)
  circle C1 centre (-18, -85) radius 2.7
extrude "Extrude4" cut sketch "M5 rail bore" along normal blind 9.2
work_plane "WorkPlane5" AlongDistance 54.9 ExtraOffset 0
sketch "Rail bore print-up roof" plane through (0, 0, 54.9) normal (0, 0, 1) x axis (1, 0, 0)
  line L1 (-19.9092, -83.0908) -> (-19.9092, -86.9092)
  line L2 (-21.8184, -85) -> (-19.9092, -83.0908)
  line L3 (-19.9092, -86.9092) -> (-21.8184, -85)
extrude "Extrude5" cut sketch "Rail bore print-up roof" along normal blind 9.2
work_plane "WorkPlane1" AlongDistance 50 ExtraOffset 0
sketch "Top rail M5x14 (-1, -1)" plane through (0, 0, 50) normal (0, 0, 1) x axis (1, 0, 0)
  circle C1 centre (-18, -85) radius 2.5
extrude "Extrude1" new body sketch "Top rail M5x14 (-1, -1)" along normal blind 14 bodies "HARDWARE Top rail M5x14 (-1, -1)"
work_plane "WorkPlane2" AlongDistance 64 ExtraOffset 0
sketch "Button head" plane through (0, 0, 64) normal (0, 0, 1) x axis (1, 0, 0)
  circle C1 centre (-18, -85) radius 4.25
extrude "Extrude2" add sketch "Button head" along normal blind 5
work_plane "WorkPlane6" AlongDistance -24 ExtraOffset 0
sketch "Broad rail tab root (1)" plane through (-24, 0, 0) normal (1, 0, 0) x axis (0, 0, -1)
  line L1 (-51, 95) -> (-51, 60)
  line L2 (-64, 95) -> (-51, 95)
  line L3 (-64, 60) -> (-64, 95)
  line L4 (-51, 60) -> (-64, 60)
extrude "Extrude6" add sketch "Broad rail tab root (1)" along normal blind 12
work_plane "WorkPlane7" AlongDistance -24.1 ExtraOffset 0
sketch "Rail seat underside (1)" plane through (-24.1, 0, 0) normal (1, 0, 0) x axis (0, 0, -1)
  line L1 (-50.9, 96) -> (-50.9, 75)
  line L2 (-55, 96) -> (-50.9, 96)
  line L3 (-55, 75) -> (-55, 96)
  line L4 (-50.9, 75) -> (-55, 75)
extrude "Extrude7" cut sketch "Rail seat underside (1)" along normal blind 12.2
work_plane "WorkPlane8" AlongDistance 54.9 ExtraOffset 0
sketch "M5 rail bore (1)" plane through (0, 0, 54.9) normal (0, 0, 1) x axis (1, 0, 0)
  circle C1 centre (-18, 85) radius 2.7
extrude "Extrude8" cut sketch "M5 rail bore (1)" along normal blind 9.2
work_plane "WorkPlane9" AlongDistance 54.9 ExtraOffset 0
sketch "Rail bore print-up roof (1)" plane through (0, 0, 54.9) normal (0, 0, 1) x axis (1, 0, 0)
  line L1 (-19.9092, 86.9092) -> (-19.9092, 83.0908)
  line L2 (-21.8184, 85) -> (-19.9092, 86.9092)
  line L3 (-19.9092, 83.0908) -> (-21.8184, 85)
extrude "Extrude9" cut sketch "Rail bore print-up roof (1)" along normal blind 9.2
work_plane "WorkPlane1" AlongDistance 50 ExtraOffset 0
sketch "Top rail M5x14 (-1, 1)" plane through (0, 0, 50) normal (0, 0, 1) x axis (1, 0, 0)
  circle C1 centre (-18, 85) radius 2.5
extrude "Extrude1" new body sketch "Top rail M5x14 (-1, 1)" along normal blind 14 bodies "HARDWARE Top rail M5x14 (-1, 1)"
work_plane "WorkPlane2" AlongDistance 64 ExtraOffset 0
sketch "Button head" plane through (0, 0, 64) normal (0, 0, 1) x axis (1, 0, 0)
  circle C1 centre (-18, 85) radius 4.25
extrude "Extrude2" add sketch "Button head" along normal blind 5
work_plane "WorkPlane10" AlongDistance -24.1 ExtraOffset 0
sketch "Main bearing seat" plane through (-24.1, 0, 0) normal (1, 0, 0) x axis (0, 0, -1)
  circle C1 centre (-30, 0) radius 10.15
extrude "Extrude10" cut sketch "Main bearing seat" along normal blind 12.2
work_plane "WorkPlane11" AlongDistance -24.1 ExtraOffset 0
sketch "Brace mounting clearance" plane through (-24.1, 0, 0) normal (1, 0, 0) x axis (0, 0, -1)
  circle C1 centre (-35, -60) radius 1.7
work_plane "WorkPlane12" AlongDistance -24.1 ExtraOffset 0
sketch "Brace mounting clearance (1)" plane through (-24.1, 0, 0) normal (1, 0, 0) x axis (0, 0, -1)
  circle C1 centre (-45, -60) radius 1.7
work_plane "WorkPlane13" AlongDistance -24.1 ExtraOffset 0
sketch "Brace mounting clearance (2)" plane through (-24.1, 0, 0) normal (1, 0, 0) x axis (0, 0, -1)
  circle C1 centre (-35, 60) radius 1.7
work_plane "WorkPlane14" AlongDistance -24.1 ExtraOffset 0
sketch "Brace mounting clearance (3)" plane through (-24.1, 0, 0) normal (1, 0, 0) x axis (0, 0, -1)
  circle C1 centre (-45, 60) radius 1.7
work_plane "WorkPlane15" AlongDistance -24.1 ExtraOffset 0
sketch "Captured follower axle blind seat" plane through (-24.1, 0, 0) normal (1, 0, 0) x axis (0, 0, -1)
  circle C1 centre (23, -35) radius 4.15
extrude "Extrude15" cut sketch "Captured follower axle blind seat" along normal blind 2.1
work_plane "WorkPlane16" AlongDistance -33.5 ExtraOffset 0
sketch "Broad cassette mounting boss" plane through (-33.5, 0, 0) normal (1, 0, 0) x axis (0, 0, -1)
  circle C1 centre (35, -55) radius 8
work_plane "WorkPlane17" AlongDistance -33.6 ExtraOffset 0
sketch "Cassette insert pocket" plane through (-33.6, 0, 0) normal (1, 0, 0) x axis (0, 0, -1)
  circle C1 centre (35, -55) radius 2
work_plane "WorkPlane18" AlongDistance -33.5 ExtraOffset 0
sketch "Broad cassette mounting boss (1)" plane through (-33.5, 0, 0) normal (1, 0, 0) x axis (0, 0, -1)
  circle C1 centre (35, -15) radius 8
work_plane "WorkPlane19" AlongDistance -33.6 ExtraOffset 0
sketch "Cassette insert pocket (1)" plane through (-33.6, 0, 0) normal (1, 0, 0) x axis (0, 0, -1)
  circle C1 centre (35, -15) radius 2
work_plane "WorkPlane20" AlongDistance -24.1 ExtraOffset 0
sketch "Spring block mounting clearance" plane through (-24.1, 0, 0) normal (1, 0, 0) x axis (0, 0, -1)
  circle C1 centre (-14, -62) radius 1.7
extrude "Extrude20" cut sketch "Spring block mounting clearance" along normal blind 12.2
work_plane "WorkPlane21" AlongDistance -24.1 ExtraOffset 0
sketch "Spring block mounting clearance (1)" plane through (-24.1, 0, 0) normal (1, 0, 0) x axis (0, 0, -1)
  circle C1 centre (-14, -48) radius 1.7
extrude "Extrude21" cut sketch "Spring block mounting clearance (1)" along normal blind 12.2
work_plane "WorkPlane22" AlongDistance -17.3 ExtraOffset 0
sketch "Stop shear spigot socket" plane through (-17.3, 0, 0) normal (1, 0, 0) x axis (0, 0, -1)
  circle C1 centre (-22.8923, -36.3109) radius 6.15
extrude "Extrude22" cut sketch "Stop shear spigot socket" along normal blind 5.4
work_plane "WorkPlane23" AlongDistance -24.1 ExtraOffset 0
sketch "Stop retaining screw passage" plane through (-24.1, 0, 0) normal (1, 0, 0) x axis (0, 0, -1)
  circle C1 centre (-22.8923, -36.3109) radius 1.7
extrude "Extrude23" cut sketch "Stop retaining screw passage" along normal blind 7
work_plane "WorkPlane24" AlongDistance -17.3 ExtraOffset 0
sketch "Stop shear spigot socket (1)" plane through (-17.3, 0, 0) normal (1, 0, 0) x axis (0, 0, -1)
  circle C1 centre (-22.8923, 36.3109) radius 6.15
extrude "Extrude24" cut sketch "Stop shear spigot socket (1)" along normal blind 5.4
work_plane "WorkPlane25" AlongDistance -24.1 ExtraOffset 0
sketch "Stop retaining screw passage (1)" plane through (-24.1, 0, 0) normal (1, 0, 0) x axis (0, 0, -1)
  circle C1 centre (-22.8923, 36.3109) radius 1.7
extrude "Extrude25" cut sketch "Stop retaining screw passage (1)" along normal blind 7
work_plane "WorkPlane1" AlongDistance 12 ExtraOffset 0
sketch "Continuous load-bearing web" plane through (12, 0, 0) normal (1, 0, 0) x axis (0, 0, -1)
  line L1 (-51.6257, 74.4508) -> (-51, 74.5)
  line L2 (-52.2361, 74.3042) -> (-51.6257, 74.4508)
  line L3 (-52.816, 74.064) -> (-52.2361, 74.3042)
  line L4 (-53.3511, 73.7361) -> (-52.816, 74.064)
  line L5 (-53.8284, 73.3284) -> (-53.3511, 73.7361)
  line L6 (-54.2361, 72.8511) -> (-53.8284, 73.3284)
  line L7 (-54.564, 72.316) -> (-54.2361, 72.8511)
  line L8 (-54.8042, 71.7361) -> (-54.564, 72.316)
  line L9 (-54.9508, 71.1257) -> (-54.8042, 71.7361)
  line L10 (-55, 70.5) -> (-54.9508, 71.1257)
  line L11 (-55, -70.5) -> (-55, 70.5)
  line L12 (-54.9508, -71.1257) -> (-55, -70.5)
  line L13 (-54.8042, -71.7361) -> (-54.9508, -71.1257)
  line L14 (-54.564, -72.316) -> (-54.8042, -71.7361)
  line L15 (-54.2361, -72.8511) -> (-54.564, -72.316)
  line L16 (-53.8284, -73.3284) -> (-54.2361, -72.8511)
  line L17 (-53.3511, -73.7361) -> (-53.8284, -73.3284)
  line L18 (-52.816, -74.064) -> (-53.3511, -73.7361)
  line L19 (-52.2361, -74.3042) -> (-52.816, -74.064)
  line L20 (-51.6257, -74.4508) -> (-52.2361, -74.3042)
  line L21 (-51, -74.5) -> (-51.6257, -74.4508)
  line L22 (33, -74.5) -> (-51, -74.5)
  line L23 (33.6257, -74.4508) -> (33, -74.5)
  line L24 (34.2361, -74.3042) -> (33.6257, -74.4508)
  line L25 (34.816, -74.064) -> (34.2361, -74.3042)
  line L26 (35.3511, -73.7361) -> (34.816, -74.064)
  line L27 (35.8284, -73.3284) -> (35.3511, -73.7361)
  line L28 (36.2361, -72.8511) -> (35.8284, -73.3284)
  line L29 (36.564, -72.316) -> (36.2361, -72.8511)
  line L30 (36.8042, -71.7361) -> (36.564, -72.316)
  line L31 (36.9508, -71.1257) -> (36.8042, -71.7361)
  line L32 (37, -70.5) -> (36.9508, -71.1257)
  line L33 (37, 70.5) -> (37, -70.5)
  line L34 (36.9508, 71.1257) -> (37, 70.5)
  line L35 (36.8042, 71.7361) -> (36.9508, 71.1257)
  line L36 (36.564, 72.316) -> (36.8042, 71.7361)
  line L37 (36.2361, 72.8511) -> (36.564, 72.316)
  line L38 (35.8284, 73.3284) -> (36.2361, 72.8511)
  line L39 (35.3511, 73.7361) -> (35.8284, 73.3284)
  line L40 (34.816, 74.064) -> (35.3511, 73.7361)
  line L41 (34.2361, 74.3042) -> (34.816, 74.064)
  line L42 (33.6257, 74.4508) -> (34.2361, 74.3042)
  line L43 (33, 74.5) -> (33.6257, 74.4508)
  line L44 (-51, 74.5) -> (33, 74.5)
extrude "Extrude1" new body sketch "Continuous load-bearing web" along normal blind 12 bodies "P02S Continuous right sensor plate"
work_plane "WorkPlane2" AlongDistance 12 ExtraOffset 0
sketch "Broad rail tab root" plane through (12, 0, 0) normal (1, 0, 0) x axis (0, 0, -1)
  line L1 (-51, -60) -> (-51, -95)
  line L2 (-64, -60) -> (-51, -60)
  line L3 (-64, -95) -> (-64, -60)
  line L4 (-51, -95) -> (-64, -95)
extrude "Extrude2" add sketch "Broad rail tab root" along normal blind 12
work_plane "WorkPlane3" AlongDistance 11.9 ExtraOffset 0
sketch "Rail seat underside" plane through (11.9, 0, 0) normal (1, 0, 0) x axis (0, 0, -1)
  line L1 (-50.9, -75) -> (-50.9, -96)
  line L2 (-55, -75) -> (-50.9, -75)
  line L3 (-55, -96) -> (-55, -75)
  line L4 (-50.9, -96) -> (-55, -96)
extrude "Extrude3" cut sketch "Rail seat underside" along normal blind 12.2
work_plane "WorkPlane4" AlongDistance 54.9 ExtraOffset 0
sketch "M5 rail bore" plane through (0, 0, 54.9) normal (0, 0, 1) x axis (1, 0, 0)
  circle C1 centre (18, -85) radius 2.7
extrude "Extrude4" cut sketch "M5 rail bore" along normal blind 9.2
work_plane "WorkPlane5" AlongDistance 54.9 ExtraOffset 0
sketch "Rail bore print-up roof" plane through (0, 0, 54.9) normal (0, 0, 1) x axis (1, 0, 0)
  line L1 (19.9092, -83.0908) -> (19.9092, -86.9092)
  line L2 (21.8184, -85) -> (19.9092, -83.0908)
  line L3 (19.9092, -86.9092) -> (21.8184, -85)
extrude "Extrude5" cut sketch "Rail bore print-up roof" along normal blind 9.2
work_plane "WorkPlane1" AlongDistance 50 ExtraOffset 0
sketch "Top rail M5x14 (1, -1)" plane through (0, 0, 50) normal (0, 0, 1) x axis (1, 0, 0)
  circle C1 centre (18, -85) radius 2.5
extrude "Extrude1" new body sketch "Top rail M5x14 (1, -1)" along normal blind 14 bodies "HARDWARE Top rail M5x14 (1, -1)"
work_plane "WorkPlane2" AlongDistance 64 ExtraOffset 0
sketch "Button head" plane through (0, 0, 64) normal (0, 0, 1) x axis (1, 0, 0)
  circle C1 centre (18, -85) radius 4.25
extrude "Extrude2" add sketch "Button head" along normal blind 5
work_plane "WorkPlane6" AlongDistance 12 ExtraOffset 0
sketch "Broad rail tab root (1)" plane through (12, 0, 0) normal (1, 0, 0) x axis (0, 0, -1)
  line L1 (-51, 95) -> (-51, 60)
  line L2 (-64, 95) -> (-51, 95)
  line L3 (-64, 60) -> (-64, 95)
  line L4 (-51, 60) -> (-64, 60)
extrude "Extrude6" add sketch "Broad rail tab root (1)" along normal blind 12
work_plane "WorkPlane7" AlongDistance 11.9 ExtraOffset 0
